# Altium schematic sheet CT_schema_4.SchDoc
size 297 x 173 mm
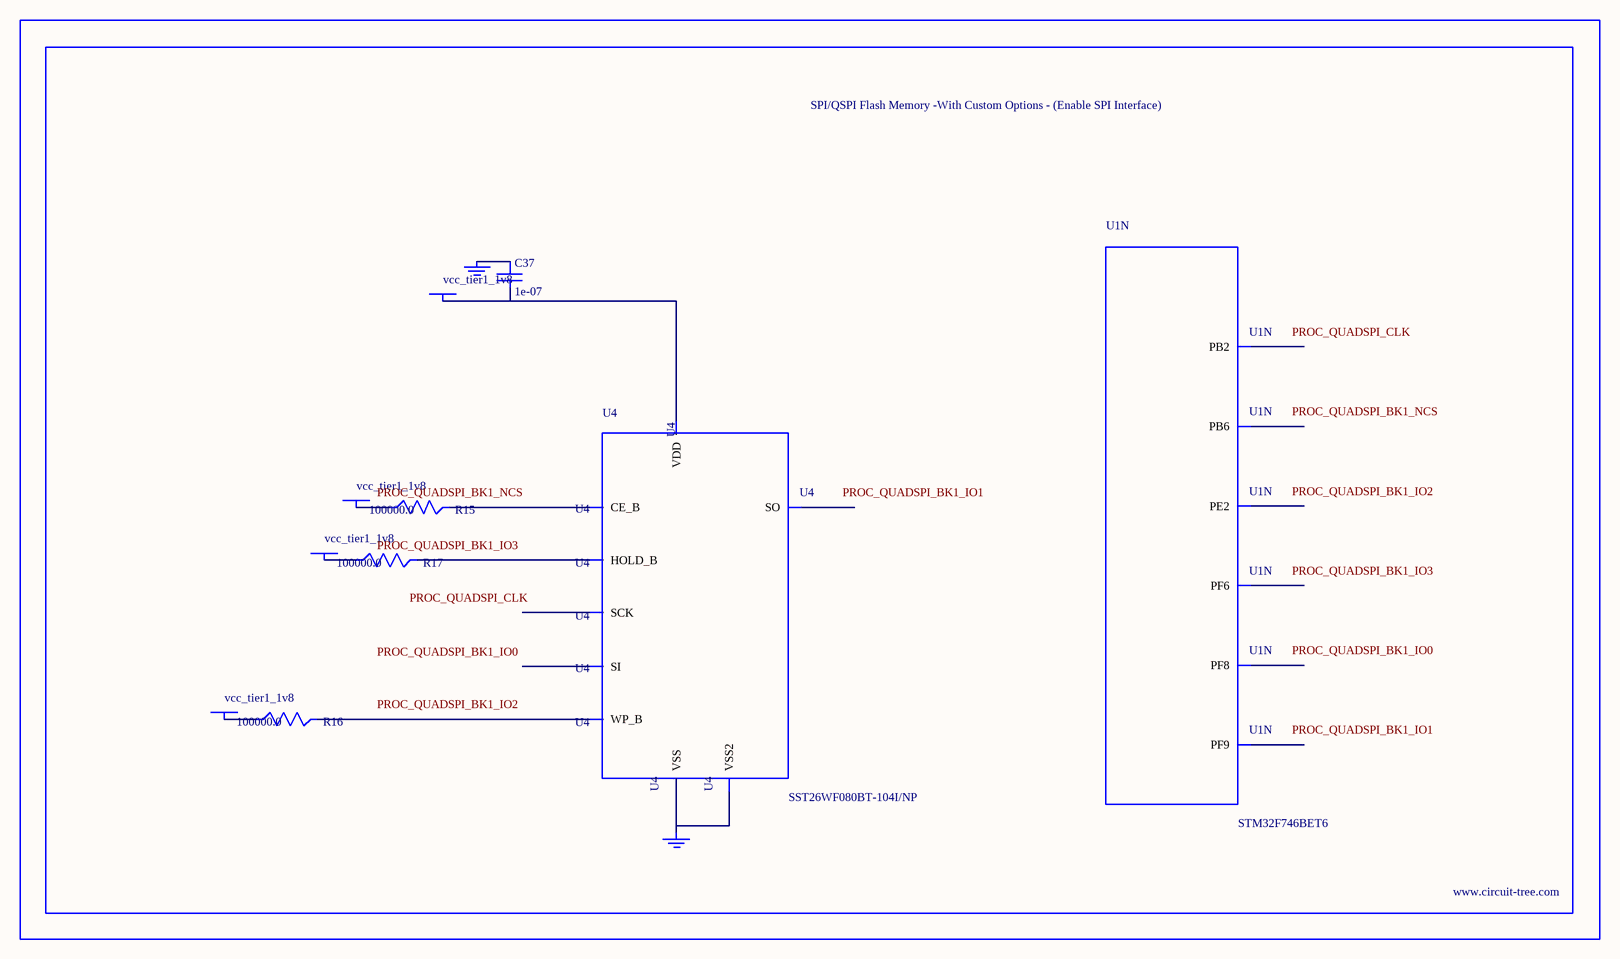
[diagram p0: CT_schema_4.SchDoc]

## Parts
BORDER3  (no value)
C37  1e-07  [C0402]
GND_INSTANCE_3_0  (no value)
GND_INSTANCE_3_1  (no value)
POWER_INSTANCE_3_0  vcc_tier1_1v8
POWER_INSTANCE_3_1  vcc_tier1_1v8
POWER_INSTANCE_3_2  vcc_tier1_1v8
POWER_INSTANCE_3_3  vcc_tier1_1v8
R15  100000.0  [R0603]
R16  100000.0  [R0603]
R17  100000.0  [R0603]
U1  STM32F746BET6  [LQFP208]  (part N of 15)
U4  SST26WF080BT-104I/NP  [USON-8]

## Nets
NetC37_1: C37.1 GND_INSTANCE_3_0.0(GND)
NetC37_2: C37.2 POWER_INSTANCE_3_3.0(PWR) U4.8(VDD)
NetGND_INSTANCE_3_1_0: GND_INSTANCE_3_1.0(GND) U4.4(VSS) U4.9(VSS2)
NetPOWER_INSTANCE_3_0_0: POWER_INSTANCE_3_0.0(PWR) R15.1
NetPOWER_INSTANCE_3_1_0: POWER_INSTANCE_3_1.0(PWR) R16.1
NetPOWER_INSTANCE_3_2_0: POWER_INSTANCE_3_2.0(PWR) R17.1
NetR15_2: R15.2 U4.1(CE_B)
NetR16_2: R16.2 U4.3(WP_B)
NetR17_2: R17.2 U4.7(HOLD_B)

Not connected (* = marked no-connect by the designer): U1 1(PE2) 27(PF6) 29(PF8) 30(PF9) 63(PB2) 195(PB6); U4 2(SO) 5(SI) 6(SCK)

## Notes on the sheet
- Labels drawn without touching a wire or pin: PROC_QUADSPI_BK1_IO0, PROC_QUADSPI_BK1_IO1, PROC_QUADSPI_BK1_IO2, PROC_QUADSPI_BK1_IO3, PROC_QUADSPI_BK1_NCS, PROC_QUADSPI_CLK

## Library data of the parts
BORDER3 = BORDER_PAGE3
C37 = C0402C104K3RACTU
GND_INSTANCE_3_0 GND_INSTANCE_3_1 = GND
POWER_INSTANCE_3_0-POWER_INSTANCE_3_3 = PWR
R15-R17 = RC0603JR-07100KL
